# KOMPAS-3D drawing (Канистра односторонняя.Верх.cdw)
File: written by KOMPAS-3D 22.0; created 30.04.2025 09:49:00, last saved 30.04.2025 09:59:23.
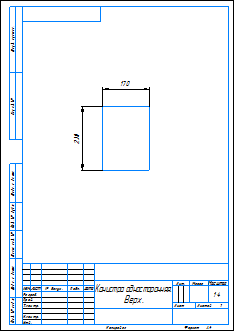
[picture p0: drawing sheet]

Sheet 1: A4, portrait

Document properties: Автор: Admin; Наименование: Канистра односторонняя. Верх; Полное имя файла: D:\28.11.2016\3D модели\Абилимпикс\2025\Канистра односторонняя\Канистра односторонняя.Верх.cdw

Title block, sheet 1: Наименование: Канистра односторонняя. / Верх.; scale: 1:4; Количество листов документа: 1; Форматы листов документа: A4; stored path: D:\28.11.2016\3D модели\Абилимпикс\2025\Канистра односторонняя\Канистра односторонняя.Зад.cdw

Dimensions and other numbers on the sheet: 230; 170; 1:4; 1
